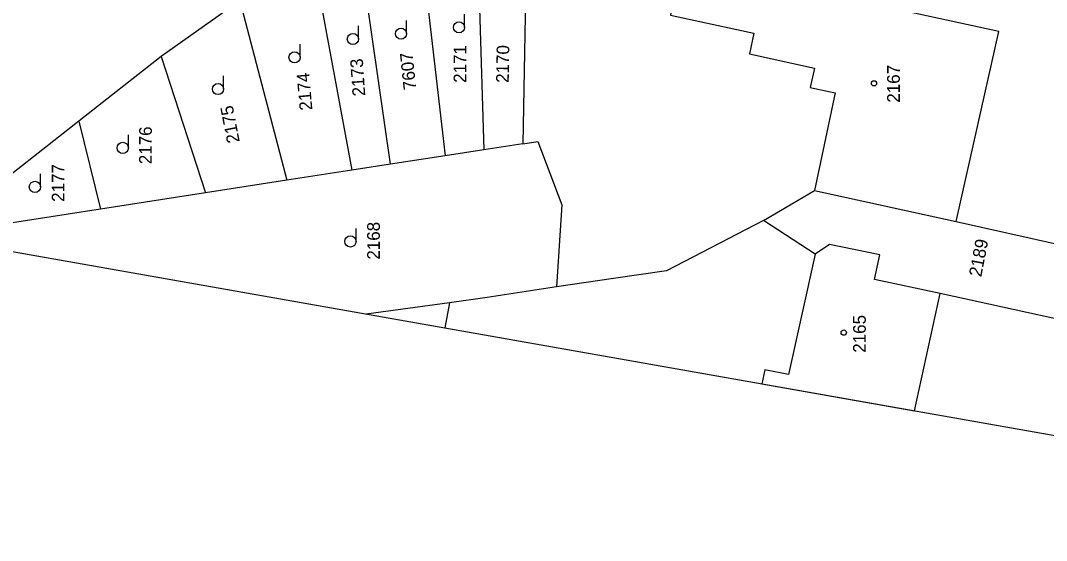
# Model space of a CAD drawing. Extents: x -534481 to -534256, y -1190577 to -1190138.
# Drawn here: x -534443.7 to -534375, y -1190577.1 to -1190542.3 of the extents above; entities that cross this region are included whole.
import ezdxf

# ---------------------------------------------------------------- set-up
doc = ezdxf.new("R2010")
doc.units = 0
for name, color, linetype in [('_rámeček', 7, 'Continuous'), ('_rámeček_mřížka', 7, 'Continuous'), ('Hranice parcel', 7, 'Continuous'), ('Parcelní čísla', 7, 'Continuous'), ('Polygon budovy', 7, 'Continuous'), ('Značky budov', 7, 'Continuous'), ('Značky kultur', 7, 'Continuous')]:
    doc.layers.add(name, color=color, linetype=linetype)

msp = doc.modelspace()

# ---------------------------------------------------------------- linework, layer by layer
at = {"layer": '_rámeček'}
for points in [[(-534407.912, -1190137.674), (-534480.845, -1190551.293), (-534334.601, -1190577.08), (-534261.668, -1190163.461)], [(-534480.845, -1190551.293), (-534334.601, -1190577.08), (-534316.367, -1190473.675)]]:
    msp.add_lwpolyline(points, dxfattribs=at)
at = {"layer": '_rámeček_mřížka'}
msp.add_lwpolyline([(-534480.845, -1190551.293), (-534334.601, -1190577.08), (-534261.668, -1190163.461)], dxfattribs=at)
at = {"layer": 'Hranice parcel'}
for p, q in [((-534409.82, -1190536.63), (-534410.07, -1190550.53)), ((-534418.94, -1190551.89), (-534421.01, -1190537.35)), ((-534416.92, -1190537.08), (-534415.27, -1190551.33)), ((-534413.12, -1190536.84), (-534412.69, -1190550.93)), ((-534424.26, -1190537.56), (-534421.51, -1190552.29)), ((-534429.03, -1190540.95), (-534434.29, -1190544.68)), ((-534429.03, -1190540.95), (-534425.87, -1190552.96)), ((-534434.29, -1190544.68), (-534439.8, -1190549.01)), ((-534434.29, -1190544.68), (-534431.32, -1190553.8)), ((-534439.8, -1190549.01), (-534449.52, -1190556.65)), ((-534439.8, -1190549.01), (-534438.35, -1190554.9)), ((-534410.07, -1190550.53), (-534412.69, -1190550.93)), ((-534412.69, -1190550.93), (-534415.27, -1190551.33)), ((-534418.94, -1190551.89), (-534421.51, -1190552.29)), ((-534415.27, -1190551.33), (-534418.94, -1190551.89)), ((-534421.51, -1190552.29), (-534425.87, -1190552.96)), ((-534425.87, -1190552.96), (-534431.32, -1190553.8)), ((-534431.32, -1190553.8), (-534438.35, -1190554.9)), ((-534438.35, -1190554.9), (-534449.52, -1190556.65)), ((-534414.97, -1190561.18), (-534420.555, -1190561.924)), ((-534414.97, -1190561.18), (-534415.295, -1190562.851))]:
    msp.add_line(p, q, dxfattribs=at)
for points in [[(-534410.07, -1190550.53), (-534409.06, -1190550.38), (-534407.46, -1190554.62), (-534407.81, -1190560.11)], [(-534393.95, -1190555.65), (-534390.54, -1190553.66), (-534381.04, -1190555.72), (-534367.07, -1190558.85)], [(-534393.95, -1190555.65), (-534400.45, -1190559.02), (-534404, -1190559.55), (-534407.81, -1190560.11)], [(-534368.89, -1190563.45), (-534382.12, -1190560.55), (-534386.52, -1190559.61), (-534386.17, -1190557.95), (-534389.54, -1190557.26), (-534390.5, -1190557.91), (-534393.95, -1190555.65)], [(-534407.81, -1190560.11), (-534412.46, -1190560.81), (-534414.97, -1190561.18)]]:
    msp.add_lwpolyline(points, dxfattribs=at)
at = {"layer": 'Polygon budovy'}
msp.add_line((-534394.068, -1190566.594), (-534383.85, -1190568.396), dxfattribs=at)
msp.add_lwpolyline([(-534400.19, -1190541.92), (-534394.59, -1190543.13), (-534394.89, -1190544.51), (-534390.54, -1190545.47), (-534390.82, -1190546.76), (-534389.15, -1190547.11), (-534390.54, -1190553.66), (-534381.04, -1190555.72), (-534378.2, -1190543), (-534387.05, -1190541.1), (-534386.59, -1190538.96), (-534391.46, -1190537.91), (-534391.92, -1190540.05), (-534399.41, -1190538.44)], close=True, dxfattribs=at)
msp.add_lwpolyline([(-534383.85, -1190568.396), (-534382.12, -1190560.55), (-534386.52, -1190559.61), (-534386.17, -1190557.95), (-534389.54, -1190557.26), (-534390.5, -1190557.91), (-534392.28, -1190565.98), (-534393.87, -1190565.65), (-534394.068, -1190566.594)], dxfattribs=at)
at = {"layer": 'Značky budov'}
for centre in [(-534386.551, -1190546.481), (-534388.578, -1190563.164)]:
    msp.add_circle(centre, 0.175, dxfattribs=at)
at = {"layer": 'Značky kultur'}
for p, q in [((-534417.851, -1190543.152), (-534417.851, -1190542.277)), ((-534413.968, -1190542.731), (-534413.968, -1190541.856)), ((-534421.078, -1190543.511), (-534421.078, -1190542.636)), ((-534424.984, -1190544.735), (-534424.984, -1190543.86)), ((-534430.108, -1190546.86), (-534430.108, -1190545.985)), ((-534436.489, -1190550.801), (-534436.489, -1190549.926)), ((-534442.371, -1190553.41), (-534442.371, -1190552.535)), ((-534421.238, -1190557.061), (-534421.238, -1190556.186))]:
    msp.add_line(p, q, dxfattribs=at)
for centre in [(-534418.227, -1190543.152), (-534414.343, -1190542.731), (-534421.453, -1190543.511), (-534425.359, -1190544.735), (-534430.483, -1190546.86), (-534436.864, -1190550.801), (-534442.746, -1190553.41), (-534421.614, -1190557.061)]:
    msp.add_circle(centre, 0.375, dxfattribs=at)

# ---------------------------------------------------------------- texts
at = {"layer": 'Parcelní čísla'}
for s, rotation, p in [('2171', 90, (-534413.853, -1190546.447)), ('2170', 89, (-534411.013, -1190546.454)), ('2173', 94, (-534420.617, -1190547.314)), ('7607', 96, (-534417.197, -1190546.879)), ('2167', 90, (-534384.821, -1190547.774)), ('2174', 95, (-534424.159, -1190548.257)), ('2175', 101, (-534429.022, -1190550.39)), ('2176', 90, (-534434.916, -1190551.893)), ('2177', 90, (-534440.765, -1190554.414)), ('2168', 90, (-534419.644, -1190558.28)), ('2189', 79, (-534379.372, -1190559.477)), ('2165', 90, (-534387.1, -1190564.514))]:
    msp.add_text(s, height=0.85, rotation=rotation, dxfattribs=at).set_placement(p)

doc.saveas('drawing.dxf')
